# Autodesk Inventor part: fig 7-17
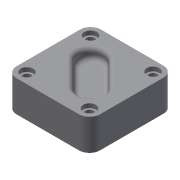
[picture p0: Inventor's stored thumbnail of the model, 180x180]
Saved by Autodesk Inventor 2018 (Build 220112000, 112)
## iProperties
Shininess: 77.0
Angle Display Precision: 2
Document Length Units: 11269
Document Angle Units: 11279
Document Time Units: 11290
Document Mass Units: 11283
Document Length Units Precision: 3
Document Angle Units Precision: 2
Created: 2001-12
Part Number: fig 7-17
Document SubType Name: Modeling
Designer: Renu Muthoo
Density: 1 g/cm^3
Material: Generic
Appearance: Default
Density: 0.0
Volumn: 0.0
Area: 0.0
PropertySet Name: Model Information
Control State: 0
Master: False
Checked Out: False
Author: Renu Muthoo
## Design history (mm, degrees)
sketch "Sketch1"
  geometry: L1 (-20, 20)-(20, 20); L2 (20, 20)-(20, -20.5); L3 (20, -20.5)-(-20, -20.5); L4 (-20, -20.5)-(-20, 20); 1 further point
  constraints: 8 end point, 2 parallel, 1 horizontal, 1 perpendicular, 1 other
  dimensions: "d0" = 40 distance of L1.start L1.end; "d1" = 40.5 distance of L3.end L1.start; "d100" = 20 distance from line of L4 point (0, 0); "d101" = 20 distance from line of L1 point (0, 0)
extrude "Extrusion1" new body sketch "Sketch1" distance "d2" = 15; taper "d3" = 0 deg
workplane "Work Plane1"
workplane "Work Plane2"
workplane "Work Plane3"
fillet "Fillet1" dims "d32" = 5
hole "Hole3" diameter "d66" = 4; stored, may be unused: countersink angle "d70" = 90 deg, drill point angle "d72" = 118 deg; dims "d64" = 10, "d65" = 10, "d67" = 6, "d68" = 6, "d69" = 2, "d71" = 8
hole "Hole4" diameter "d75" = 4; stored, may be unused: countersink angle "d79" = 90 deg, drill point angle "d81" = 118 deg; dims "d73" = 10, "d74" = 10, "d76" = 6, "d77" = 6, "d78" = 2, "d80" = 8
hole "Hole5" diameter "d84" = 4; stored, may be unused: countersink angle "d88" = 90 deg, drill point angle "d90" = 118 deg; dims "d82" = 10, "d83" = 10, "d85" = 6, "d86" = 6, "d87" = 2, "d89" = 8
hole "Hole6" diameter "d93" = 4; stored, may be unused: countersink angle "d97" = 90 deg, drill point angle "d99" = 118 deg; dims "d91" = 10, "d92" = 10, "d94" = 6, "d95" = 6, "d96" = 2, "d98" = 8
fillet "Fillet2" dims "d61" = 2
body "Solid1"
sketch "Sketch8"
  geometry: L1 (-9.844, 1.64)-(1.983, -10.187); L2 (10.469, -1.701)-(-1.358, 10.126); A1 r 6 centre (-5.601, 5.883) between (-1.358, 10.126) and (-9.844, 1.64); A2 r 6 centre (6.226, -5.944) between (1.983, -10.187) and (10.469, -1.701)
  constraints: 4 end point, 4 point on circle, 4 tangent, 2 centre point, 1 parallel
  dimensions: "d29" = 6 radius of A2
extrude "Extrusion2" cut sketch "Sketch8" distance "d30" = 5; taper "d31" = 0 deg
